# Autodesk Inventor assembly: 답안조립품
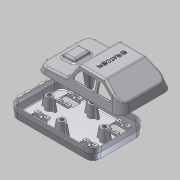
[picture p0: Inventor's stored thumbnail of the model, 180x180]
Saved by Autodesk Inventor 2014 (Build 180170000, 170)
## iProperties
Created: 2015-05
Part Number: 답안조립품
Document SubType Name: Assembly
Designer: Administrator
Author: Administrator
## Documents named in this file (3)
- C:\Documents and Settings\Administrator\바탕 화면\450508V1015\답안조립품.iam
- C:\Documents and Settings\Administrator\바탕 화면\450508V1015\본체.ipt
- C:\Documents and Settings\Administrator\바탕 화면\450508V1015\커버.ipt
